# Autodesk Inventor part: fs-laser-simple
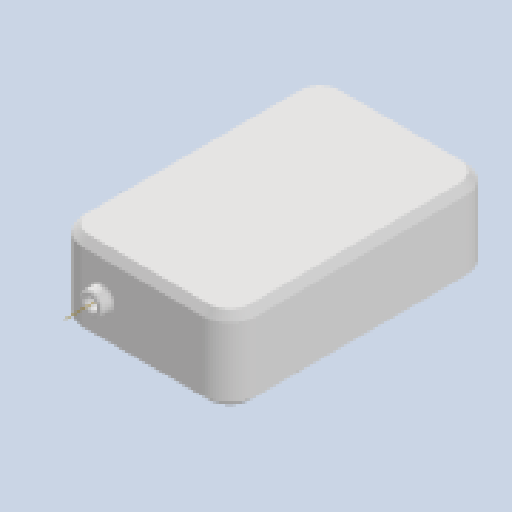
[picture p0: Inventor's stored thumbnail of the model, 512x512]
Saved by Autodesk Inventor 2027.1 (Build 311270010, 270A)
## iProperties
Created: 2026-07
Part Number: fs-laser-simple
Material: Generic
Document SubType Name: Modeling
Designer: dunge
Density: 1 g/cm^3
Appearance: Default
Author: dunge
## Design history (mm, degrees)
sketch "Sketch1"
  geometry: L1 (21.316, -5.227)-(-75.969, -5.227); L2 (-75.969, -5.227)-(-75.969, -150.182); L3 (-75.969, -150.182)-(21.316, -150.182); L4 (21.316, -150.182)-(21.316, -5.227); L5 (2.54, 0)-(5.08, 0); L6 (5.08, 0)-(5.08, -5.227); L7 (5.08, -5.227)-(2.54, -5.227); L8 (2.54, -5.227)-(2.54, 0); L9 (0, 0)-(0, -5.227); 1 further point
  constraints: 18 end point, 4 parallel, 3 perpendicular, 2 horizontal, 2 point on line, 1 horizontal alignment
  dimensions: "d0" = 2.54 distance between parallel lines of L9 L8; "d1" = 2.54 distance between parallel lines of L8 L6
extrude "Extrusion1" new body sketch "Sketch1" stored distance "d2" = 38.1; taper "d3" = 0 deg
revolve "Revolution1" stored, may be unused: angle "d4" = 90 deg
workaxis "Work Axis1"
workpoint "Work Point1"
fillet "Fillet1" dims "d5" = 12.7
chamfer "Chamfer1" distance "d6" = 3.175; stored, may be unused: second distance "d7" = 3.175, angle "d8" = 45 deg
chamfer "Chamfer2" distance "d9" = 0.635; stored, may be unused: second distance "d10" = 3.175, angle "d11" = 45 deg
body "Solid1"
